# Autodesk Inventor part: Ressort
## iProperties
Author: Flavien MARTY
Shininess: 27.0
PropertySet Name: _Private Model Information
Created: 2001-10
Part Number: Ressort
Material: Par défaut
Document SubType Name: Modélisation
Designer: Flavien MARTY
Control State: 0
Master: False
Checked Out: False
PropertySet Name: Design Tracking Control
Density: 0.0
Volumn: 0.0
Area: 0.0
PropertySet Name: Model Information
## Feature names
1. Hélicoïde1
2. Hélicoïde2
3. Hélicoïde3
4. Révolution1 [Revolution]
